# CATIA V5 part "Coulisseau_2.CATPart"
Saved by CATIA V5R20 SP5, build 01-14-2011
Part number: Coulisseau_2
Bounding box of the stored display mesh (mm): x -17.436 to -7.436, y 90.503 to 106.503, z 0 to 12
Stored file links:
  D:\thinkmotion-MPB\Dropbox\IAO_2011\MMS_GR3\IAO_2011_1523_mkessler\mkessler\mkessler_IAO\mkessler_INIT\Coulisseau_2.CATPart
  C:\Users\MARLENE\Documents\IFMA\S3\IAO\Copie de CAO\Assemblage_final.CATProduct
  D:\thinkmotion-MPB\Dropbox\IAO_2011\MMS_GR3\IAO_2011_1523_mkessler\mkessler\mkessler_IAO\mkessler_INIT\Squelette_coulisseau_2.CATPart
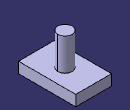
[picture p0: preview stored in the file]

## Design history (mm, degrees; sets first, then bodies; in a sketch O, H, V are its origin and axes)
External parameters (linked from other documents)
  External.Longueur_coulisseau_2 = 16 mm
  External.Largeur_coulisseau_2 = 10 mm
Set1
  Plane1: linked copy from another document
  Line1 to Line3: linked copy from another document
  Point1: linked copy from another document
Body1 (main body)
  Sketch1 on Plane1, origin (0, 0, 0), H (1, 0, 0), V (0, 1, 0)
    projected line E1 (-17.4355, 106.5026) -> (-7.4355, 106.5026) from Line1
    projected line E2 (-7.4355, 90.5026) -> (-7.4355, 106.5026) from Line2
    projected line E3 (-7.4355, 90.5026) -> (-17.4355, 90.5026) from Line3
    line L1 (-17.4355, 106.5026) -> (-17.4355, 90.5026)
    vertical: L1 V
  Pad1: profile Sketch1, direction (0, 0, 1), length 3
  Sketch2 on end face of Pad1, origin (0, 0, 3), H (1, 0, 0), V (0, 1, 0)
    circle A1 centre (-12.4355, 98.5026) radius 2
    reference projected point E1 (-12.4355, 98.5026) from Point1
    radius A1 = 2
    concentricity: E1 A1
  Pad2: profile Sketch2, direction (0, 0, 1), length 9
